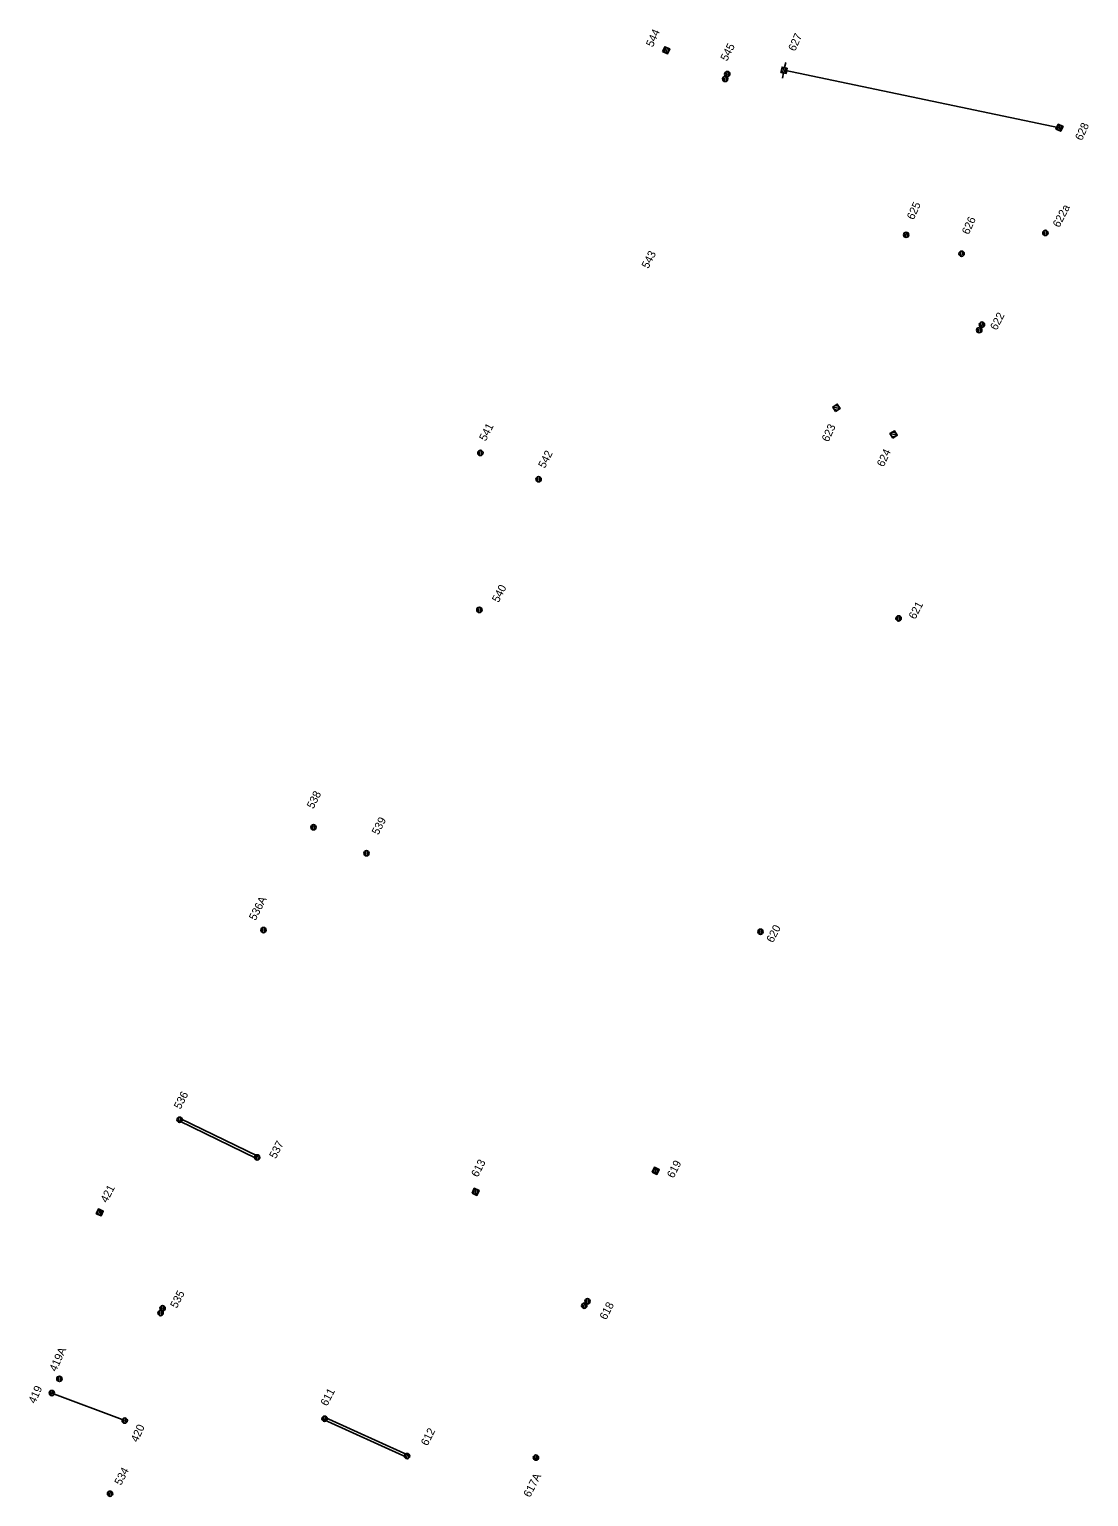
# Model space of a CAD drawing. Extents: x -595867 to -593796, y -1159595 to -1157495.
# Drawn here: x -594814.2 to -594615.7, y -1158840.2 to -1158565.2 of the extents above; entities that cross this region are included whole.
import ezdxf

# ---------------------------------------------------------------- set-up
doc = ezdxf.new("R2010")
doc.units = 0
for name, color, linetype in [('BVK_kanalizace_jednotna_nova', 7, 'Continuous'), ('DKM18', 7, 'Continuous'), ('SO31_06_54_1-protlak', 7, 'Continuous'), ('Vrstva 2', 7, 'Continuous')]:
    doc.layers.add(name, color=color, linetype=linetype)

# ---------------------------------------------------------------- blocks, each defined once
blk = doc.blocks.new('C661_2')
at = {"layer": 'SO31_06_54_1-protlak'}
for p, q in [((-0.005, 0.0003), (-0.0003, 0.005)), ((-0.005, -0.005), (0.005, 0.005)), ((0.0003, -0.005), (0.005, -0.0003))]:
    blk.add_line(p, q, dxfattribs=at)
blk.add_lwpolyline([(-0.005, 0.005), (0.005, 0.005), (0.005, -0.005), (-0.005, -0.005)], close=True, dxfattribs=at)
blk.add_lwpolyline([(-0.005, 0.005), (0.005, 0.005), (0.005, -0.005), (-0.005, -0.005), (-0.005, 0.005)], dxfattribs=at)
blk = doc.blocks.new('C666_1')
at = {"layer": 'SO31_06_54_1-protlak'}
for p, q in [((-0.005, 0), (-0.015, 0)), ((-0.005, 0.0001), (-0.0001, 0.005)), ((-0.0048, -0.005), (0.005, 0.0048)), ((0.0005, -0.005), (0.005, -0.0005)), ((0.0049, 0), (0.015, 0))]:
    blk.add_line(p, q, dxfattribs=at)
blk.add_lwpolyline([(-0.005, 0.005), (0.005, 0.005), (0.005, -0.005), (-0.005, -0.005)], close=True, dxfattribs=at)
blk.add_lwpolyline([(-0.005, 0.005), (0.005, 0.005), (0.005, -0.005), (-0.005, -0.005), (-0.005, 0.005)], dxfattribs=at)

msp = doc.modelspace()

# ---------------------------------------------------------------- linework, layer by layer
at = {"layer": 'BVK_kanalizace_jednotna_nova'}
for p, q in [((-594683.91, -1158575.01), (-594684.07, -1158574.11)), ((-594683.54, -1158574.96), (-594683.7, -1158574.04)), ((-594683.52, -1158574.09), (-594683.68, -1158573.19)), ((-594683.15, -1158574.03), (-594683.31, -1158573.12)), ((-594649.98, -1158604.22), (-594650.14, -1158603.32)), ((-594649.61, -1158604.16), (-594649.78, -1158603.25)), ((-594623.89, -1158603.86), (-594624.05, -1158602.96)), ((-594623.52, -1158603.8), (-594623.68, -1158602.89)), ((-594639.58, -1158607.76), (-594639.74, -1158606.86)), ((-594639.21, -1158607.71), (-594639.37, -1158606.79)), ((-594636.29, -1158622.09), (-594636.45, -1158621.19)), ((-594635.92, -1158622.03), (-594636.08, -1158621.12)), ((-594635.78, -1158621.05), (-594635.94, -1158620.15)), ((-594635.41, -1158621), (-594635.57, -1158620.08)), ((-594662.54, -1158635.88), (-594663.2, -1158635.73)), ((-594662.26, -1158636.32), (-594663.64, -1158636.02)), ((-594662.71, -1158636.61), (-594663.35, -1158636.47)), ((-594651.55, -1158641.31), (-594652.93, -1158641.01)), ((-594651.83, -1158640.87), (-594652.49, -1158640.72)), ((-594652, -1158641.6), (-594652.64, -1158641.46)), ((-594729.79, -1158645.11), (-594729.95, -1158644.21)), ((-594729.42, -1158645.05), (-594729.58, -1158644.14)), ((-594718.89, -1158650.03), (-594719.05, -1158649.13)), ((-594718.52, -1158649.97), (-594718.69, -1158649.06)), ((-594729.99, -1158674.52), (-594730.15, -1158673.62)), ((-594729.62, -1158674.46), (-594729.79, -1158673.55)), ((-594651.35, -1158676.12), (-594651.62, -1158675.25)), ((-594650.99, -1158676.02), (-594651.26, -1158675.14)), ((-594761.08, -1158715.27), (-594761.24, -1158714.37)), ((-594760.71, -1158715.21), (-594760.88, -1158714.3)), ((-594751.14, -1158720.14), (-594751.3, -1158719.24)), ((-594750.77, -1158720.08), (-594750.94, -1158719.17)), ((-594770.45, -1158734.52), (-594770.61, -1158733.62)), ((-594770.08, -1158734.47), (-594770.24, -1158733.55)), ((-594677.23, -1158734.85), (-594677.5, -1158733.98)), ((-594676.87, -1158734.75), (-594677.14, -1158733.86)), ((-594786.18, -1158770.08), (-594786.34, -1158769.18)), ((-594785.81, -1158770.03), (-594785.97, -1158769.11)), ((-594771.65, -1158777.13), (-594771.81, -1158776.23)), ((-594771.28, -1158777.07), (-594771.45, -1158776.16)), ((-594709.66, -1158804.11), (-594709.93, -1158803.24)), ((-594709.3, -1158804.01), (-594709.57, -1158803.12)), ((-594789.75, -1158806.32), (-594789.91, -1158805.42)), ((-594789.38, -1158806.26), (-594789.54, -1158805.35)), ((-594789.37, -1158805.41), (-594789.53, -1158804.51)), ((-594789, -1158805.35), (-594789.16, -1158804.44)), ((-594710.27, -1158804.95), (-594710.53, -1158804.08)), ((-594709.9, -1158804.85), (-594710.17, -1158803.96)), ((-594808.72, -1158818.65), (-594808.88, -1158817.75)), ((-594808.35, -1158818.59), (-594808.51, -1158817.68)), ((-594810.14, -1158821.31), (-594810.3, -1158820.41)), ((-594809.77, -1158821.25), (-594809.94, -1158820.34)), ((-594796.11, -1158826.43), (-594796.28, -1158825.51)), ((-594758.95, -1158826.12), (-594759.22, -1158825.25)), ((-594758.59, -1158826.02), (-594758.86, -1158825.14)), ((-594796.48, -1158826.48), (-594796.64, -1158825.58)), ((-594743.49, -1158833.13), (-594743.76, -1158832.26)), ((-594743.13, -1158833.03), (-594743.4, -1158832.15)), ((-594719.32, -1158833.42), (-594719.59, -1158832.55)), ((-594718.96, -1158833.32), (-594719.23, -1158832.43)), ((-594799.21, -1158840.18), (-594799.37, -1158839.28)), ((-594798.84, -1158840.12), (-594799, -1158839.21))]:
    msp.add_line(p, q, dxfattribs=at)
for points in [[(-594621.13, -1158583.67), (-594672.75, -1158572.9)], [(-594663.1, -1158636.86), (-594663.64, -1158636.02), (-594662.8, -1158635.48), (-594662.26, -1158636.32), (-594663.1, -1158636.86)], [(-594652.39, -1158641.85), (-594652.93, -1158641.01), (-594652.09, -1158640.47), (-594651.55, -1158641.31), (-594652.39, -1158641.85)], [(-594771.65, -1158776.87), (-594786.18, -1158769.82)], [(-594771.43, -1158776.43), (-594785.96, -1158769.38)], [(-594810.03, -1158820.83), (-594796.37, -1158826)], [(-594743.33, -1158832.41), (-594758.8, -1158825.4)], [(-594743.54, -1158832.87), (-594759, -1158825.86)]]:
    msp.add_lwpolyline(points, dxfattribs=at)
for points in [[(-594663.1, -1158636.86), (-594663.64, -1158636.02), (-594662.8, -1158635.48), (-594662.26, -1158636.32)], [(-594652.39, -1158641.85), (-594652.93, -1158641.01), (-594652.09, -1158640.47), (-594651.55, -1158641.31)]]:
    msp.add_lwpolyline(points, close=True, dxfattribs=at)
for centre in [(-594683.8, -1158574.53), (-594683.8, -1158574.53), (-594683.41, -1158573.61), (-594683.41, -1158573.61), (-594649.87, -1158603.74), (-594649.87, -1158603.74), (-594623.78, -1158603.38), (-594623.78, -1158603.38), (-594639.47, -1158607.28), (-594639.47, -1158607.28), (-594636.18, -1158621.61), (-594636.18, -1158621.61), (-594635.67, -1158620.57), (-594635.67, -1158620.57), (-594729.68, -1158644.63), (-594729.68, -1158644.63), (-594718.78, -1158649.55), (-594718.78, -1158649.55), (-594729.88, -1158674.04), (-594729.88, -1158674.04), (-594651.3, -1158675.63), (-594651.3, -1158675.63), (-594760.97, -1158714.79), (-594760.97, -1158714.79), (-594751.03, -1158719.66), (-594751.03, -1158719.66), (-594770.34, -1158734.04), (-594770.34, -1158734.04), (-594677.18, -1158734.36), (-594677.18, -1158734.36), (-594786.07, -1158769.6), (-594786.07, -1158769.6), (-594771.54, -1158776.65), (-594771.54, -1158776.65), (-594709.61, -1158803.62), (-594709.61, -1158803.62), (-594789.64, -1158805.84), (-594789.64, -1158805.84), (-594789.26, -1158804.93), (-594789.26, -1158804.93), (-594710.21, -1158804.46), (-594710.21, -1158804.46), (-594808.61, -1158818.17), (-594808.61, -1158818.17), (-594810.03, -1158820.83), (-594810.03, -1158820.83), (-594796.37, -1158826), (-594796.37, -1158826), (-594758.9, -1158825.63), (-594758.9, -1158825.63), (-594743.44, -1158832.64), (-594743.44, -1158832.64), (-594719.27, -1158832.93), (-594719.27, -1158832.93), (-594799.1, -1158839.7), (-594799.1, -1158839.7)]:
    msp.add_circle(centre, 0.5, dxfattribs=at)

# ---------------------------------------------------------------- block references
for name, p, xscale, yscale, rotation in [('C661_2', (-594694.86, -1158569.15), 99.99984047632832, 99.9998404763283, 66.01657048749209), ('C666_1', (-594672.75, -1158572.9), 99.99971696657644, 99.99971696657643, -101.0889640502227), ('C661_2', (-594621.13, -1158583.67), 99.99957555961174, 99.99957555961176, 65.30990745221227)]:
    msp.add_blockref(name, p, dxfattribs=dict(at, xscale=xscale, yscale=yscale, rotation=rotation))
at = {"layer": 'Vrstva 2', "xscale": 99.99957555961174, "yscale": 99.99957555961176, "rotation": 65.30990745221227}
for p in [(-594696.83, -1158779.18), (-594730.59, -1158783.11), (-594801.05, -1158786.98)]:
    msp.add_blockref('C661_2', p, dxfattribs=at)

# ---------------------------------------------------------------- texts
at = {"layer": 'BVK_kanalizace_jednotna_nova'}
for s, rotation, p in [('544', 65.5984, (-594697.37, -1158568.67)), ('627', 65.5984, (-594670.71, -1158569.46)), ('545', 62.6209, (-594683.46, -1158571.31)), ('628', 65.5984, (-594616.93, -1158586.2)), ('625', 65.5984, (-594648.47, -1158601.04)), ('622a', 62.6209, (-594621.17, -1158602.49)), ('626', 65.5984, (-594638.15, -1158603.81)), ('543', 62.6209, (-594698.24, -1158610.2)), ('622', 62.6209, (-594632.91, -1158621.75)), ('541', 62.6209, (-594728.69, -1158642.52)), ('623', 65.5984, (-594664.43, -1158642.67)), ('624', 65.5984, (-594654.09, -1158647.36)), ('542', 62.6209, (-594717.62, -1158647.62)), ('540', 62.6209, (-594726.28, -1158672.78)), ('621', 62.6209, (-594648.18, -1158675.93)), ('538', 62.6209, (-594761.01, -1158711.44)), ('539', 62.6209, (-594748.83, -1158716.34)), ('536A', 62.6209, (-594771.85, -1158732.38)), ('620', 62.6209, (-594674.85, -1158736.54)), ('536', 62.6209, (-594785.92, -1158767.76)), ('537', 62.6209, (-594768.04, -1158777.02)), ('613', 62.6209, (-594730.19, -1158780.49)), ('619', 62.6209, (-594693.49, -1158780.67)), ('618', 62.6209, (-594706.12, -1158807.22)), ('419A', 65.5984, (-594809.22, -1158816.93)), ('419', 65.5984, (-594813.15, -1158822.92)), ('611', 62.6209, (-594758.43, -1158823.39)), ('420', 65.5984, (-594793.95, -1158830.17)), ('612', 62.6209, (-594739.62, -1158830.84)), ('617A', 62.6209, (-594720.4, -1158840.5))]:
    msp.add_text(s, height=1.5, rotation=rotation, dxfattribs=at).set_placement(p)
at = {"layer": 'DKM18'}
for s, p in [('421', (-594799.69, -1158785.28)), ('535', (-594786.61, -1158805.06)), ('534', (-594797.06, -1158838.24))]:
    msp.add_text(s, height=1.5, rotation=62.6209, dxfattribs=at).set_placement(p)

doc.saveas('drawing.dxf')
